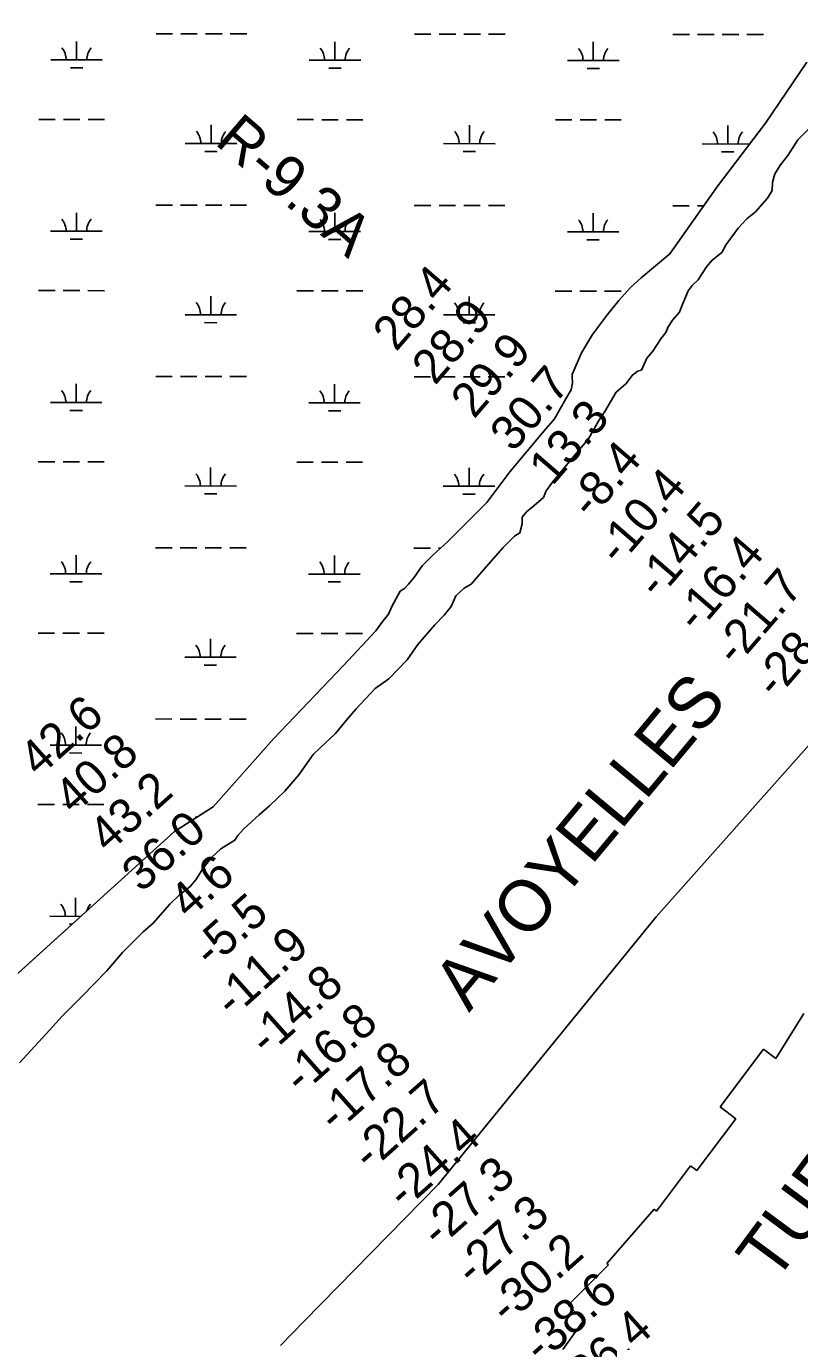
# Model space of a CAD drawing. Extents: x 3148686 to 3186545, y 916144 to 941516.
# Drawn here: x 3155629 to 3157131, y 922106 to 924661 of the extents above; entities that cross this region are included whole.
import ezdxf

# ---------------------------------------------------------------- set-up
doc = ezdxf.new("R2010")
doc.units = 0
for name, color, linetype in [('V-RIVR-EDGE', 7, 'Continuous'), ('V-RIVR-RANG', 7, 'Continuous'), ('V-RIVR-RANG-IDEN', 7, 'Continuous'), ('V-RRAP-RVMT', 7, 'Continuous'), ('V-RRAP-RVMT-IDEN', 7, 'Continuous'), ('V-SITE-VEGE', 7, 'Continuous'), ('V-TOPO-BNDY', 7, 'Continuous'), ('V-TOPO-GNAM-IDEN', 7, 'Continuous'), ('V-WETL-SWMP', 7, 'Continuous')]:
    doc.layers.add(name, color=color, linetype=linetype)

msp = doc.modelspace()

# ---------------------------------------------------------------- linework, layer by layer
at = {"layer": 'V-RIVR-EDGE'}
for points in [[(3157165.5, 924478.7), (3157127.5, 924440.5), (3157108.3, 924409.7), (3157093.7, 924392), (3157082.7, 924374), (3157078.4, 924358.4), (3157077.6, 924341.7), (3157068.4, 924326.9), (3157045.2, 924300.7), (3157028.2, 924287.2), (3157011.5, 924268.8), (3156988.3, 924237.3), (3156979.8, 924221.8), (3156961.3, 924206.6), (3156949.9, 924193.8), (3156941.8, 924180.4), (3156933.9, 924168.7), (3156922.2, 924157.4), (3156914.7, 924147.1), (3156901.5, 924115.9), (3156897.6, 924105.7), (3156884.4, 924090.1), (3156875.5, 924077), (3156871.3, 924066), (3156861.7, 924053.6), (3156846, 924029.9), (3156833.9, 924016.1), (3156829.3, 924004.4), (3156823.6, 923992.7), (3156816.1, 923991.3), (3156805.5, 923982.8), (3156794.1, 923966.9), (3156774.9, 923949.9), (3156752.8, 923912.8), (3156741.1, 923895.4), (3156720.8, 923859.3), (3156686.3, 923818.6), (3156651, 923775.1), (3156638.6, 923758.4), (3156633.2, 923745.3), (3156614.8, 923729.4), (3156600.6, 923718.1), (3156592, 923707.1), (3156592, 923694.7), (3156587.3, 923676.7), (3156577.4, 923670.7), (3156555.4, 923648.7), (3156517.7, 923605.9), (3156492.8, 923577.6), (3156479.6, 923569.5), (3156463.3, 923554.6), (3156454.4, 923534.1)], [(3156454.4, 923534.1), (3156440.8, 923517.1), (3156422.4, 923498), (3156389.6, 923459.8), (3156368.6, 923430.4), (3156332.7, 923393.3), (3156306.5, 923374.5), (3156269.5, 923335.3), (3156249.9, 923312.6), (3156229.7, 923287.5), (3156199.8, 923259.6), (3156186.3, 923246.5), (3156158.2, 923206.8), (3156131.2, 923175.3), (3156101.3, 923147), (3156081, 923129.4), (3156051.2, 923102.1), (3156039.5, 923089.4), (3156033.8, 923079.8), (3156006.8, 923063.2), (3155989, 923047.3), (3155972.6, 923025.4), (3155958, 923003.1), (3155947.4, 922990), (3155926.4, 922974.1), (3155907.6, 922955.7), (3155875.2, 922918.9), (3155856, 922901.9), (3155815.9, 922861.6), (3155784.9, 922826.2), (3155736.9, 922776.3), (3155698.9, 922738.8), (3155667.2, 922703.8), (3155615.3, 922647.6)]]:
    msp.add_lwpolyline(points, dxfattribs=at)
at = {"layer": 'V-RRAP-RVMT'}
for p, q in [((3157084.6, 922656.1), (3157139.3, 922743.6)), ((3156976.6, 922561.9), (3157061.1, 922673.9)), ((3157061.1, 922673.9), (3157084.6, 922656.1)), ((3157007.4, 922538.8), (3156976.6, 922561.9)), ((3156931.6, 922438.2), (3157007.4, 922538.8)), ((3156852.7, 922359.6), (3156919.1, 922447.6)), ((3156919.1, 922447.6), (3156931.6, 922438.2)), ((3156756.6, 922257.6), (3156848.5, 922363.3)), ((3156848.5, 922363.3), (3156852.7, 922359.6)), ((3156681.4, 922177), (3156759.5, 922255)), ((3156759.5, 922255), (3156756.6, 922257.6)), ((3156711.5, 922146.9), (3156681.4, 922177)), ((3156671.1, 922090.6), (3156711.5, 922146.9))]:
    msp.add_line(p, q, dxfattribs=at)
at = {"layer": 'V-SITE-VEGE'}
for p, q in [((3157064.5, 924472.8), (3157145.2, 924591)), ((3156972.1, 924350.8), (3157064.5, 924472.8)), ((3156879.2, 924218.9), (3156972.1, 924350.8)), ((3156823.1, 924172.6), (3156879.2, 924218.9)), ((3156802.8, 924153.8), (3156823.1, 924172.6)), ((3156779.6, 924128.5), (3156802.8, 924153.8)), ((3156758, 924101.3), (3156779.6, 924128.5)), ((3156728.9, 924062.5), (3156758, 924101.3)), ((3156707.2, 924026.9), (3156728.9, 924062.5)), ((3156689, 923984.8), (3156707.2, 924026.9)), ((3156687, 923954.8), (3156689.8, 923968.4)), ((3156689.3, 923980.3), (3156689, 923984.8)), ((3156689.8, 923968.4), (3156689.3, 923980.3)), ((3156676.6, 923937.5), (3156687, 923954.8)), ((3156654.8, 923898.1), (3156676.6, 923937.5)), ((3156631, 923870.8), (3156654.8, 923898.1)), ((3156568, 923795.5), (3156631, 923870.8)), ((3156523.7, 923735.6), (3156568, 923795.5)), ((3156446.9, 923659.6), (3156523.7, 923735.6)), ((3156418.8, 923633.8), (3156446.9, 923659.6)), ((3156397.7, 923612.6), (3156418.8, 923633.8)), ((3156381.8, 923589.9), (3156397.7, 923612.6)), ((3156371.5, 923577.1), (3156381.8, 923589.9)), ((3156339.1, 923533.7), (3156355.3, 923563.5)), ((3156355.3, 923563.5), (3156363.3, 923568.9)), ((3156363.3, 923568.9), (3156371.5, 923577.1)), ((3156332.2, 923519.2), (3156339.1, 923533.7)), ((3156319.7, 923503), (3156332.2, 923519.2)), ((3156244.8, 923419.4), (3156307.5, 923486.9)), ((3156307.5, 923486.9), (3156319.7, 923503)), ((3156109, 923276.9), (3156244.8, 923419.4)), ((3155992, 923145), (3156109, 923276.9)), ((3155916.4, 923097.1), (3155992, 923145)), ((3155545.1, 922760.8), (3155916.4, 923097.1))]:
    msp.add_line(p, q, dxfattribs=at)
at = {"layer": 'V-TOPO-BNDY'}
msp.add_lwpolyline([(3156122.4, 922098.2), (3156168.8, 922145.8), (3156428.7, 922411), (3156852.6, 922931.2), (3157254.5, 923382.8), (3157305.3, 923439.5), (3157317.3, 923453.1), (3157677.4, 924009.7), (3157746.6, 924116.6), (3157949.7, 924442.8), (3158078.5, 924650.3), (3158117.2, 924712.4), (3158363.3, 925108.2), (3158430.5, 925235.2), (3158537.2, 925435.5), (3158721.6, 925781.3), (3158837.1, 925997.9), (3159006.2, 926311.1), (3159280.9, 926819.7)], dxfattribs=at)
at = {"layer": 'V-WETL-SWMP'}
for p, q in [((3155726.3, 924595.5), (3155726.4, 924631.5)), ((3155881, 924646.1), (3155913, 924646)), ((3155929, 924646), (3155961, 924646)), ((3155977, 924646), (3156009, 924645.9)), ((3156025, 924645.9), (3156057, 924645.9)), ((3156228.3, 924595), (3156228.3, 924631)), ((3156382.9, 924645.5), (3156414.9, 924645.5)), ((3156430.9, 924645.5), (3156462.9, 924645.4)), ((3156478.9, 924645.4), (3156510.9, 924645.4)), ((3156526.9, 924645.4), (3156558.9, 924645.3)), ((3156730.2, 924594.4), (3156730.2, 924630.4)), ((3156884.8, 924645), (3156916.8, 924645)), ((3156932.8, 924645), (3156964.8, 924644.9)), ((3156980.8, 924644.9), (3157012.8, 924644.9)), ((3157028.8, 924644.9), (3157060.8, 924644.8)), ((3155676.3, 924595.5), (3155776.3, 924595.4)), ((3155714.3, 924580.1), (3155738.3, 924580)), ((3156178.3, 924595), (3156278.3, 924594.9)), ((3156216.2, 924579.5), (3156240.2, 924579.5)), ((3156680.2, 924594.5), (3156780.2, 924594.4)), ((3156718.1, 924579), (3156742.1, 924579)), ((3155652.8, 924480.1), (3155684.8, 924480.1)), ((3155700.8, 924480.1), (3155732.8, 924480)), ((3155748.8, 924480), (3155780.8, 924480)), ((3156154.7, 924479.6), (3156186.7, 924479.6)), ((3156202.7, 924479.5), (3156234.7, 924479.5)), ((3156250.7, 924479.5), (3156282.7, 924479.5)), ((3156656.6, 924479.1), (3156688.6, 924479)), ((3156704.6, 924479), (3156736.6, 924479)), ((3156752.6, 924479), (3156784.6, 924478.9)), ((3155987.6, 924433.3), (3155987.6, 924469.3)), ((3156489.5, 924432.8), (3156489.6, 924468.8)), ((3156991.4, 924432.3), (3156991.5, 924468.3)), ((3155937.6, 924433.4), (3156037.6, 924433.3)), ((3156439.5, 924432.9), (3156539.5, 924432.8)), ((3156941.4, 924432.3), (3157033.8, 924432.2)), ((3155975.6, 924417.9), (3155999.6, 924417.9)), ((3156477.5, 924417.4), (3156501.5, 924417.4)), ((3156979.4, 924416.9), (3157003.4, 924416.8)), ((3155726, 924262.8), (3155726, 924298.8)), ((3155880.6, 924313.4), (3155912.6, 924313.4)), ((3155928.6, 924313.3), (3155960.6, 924313.3)), ((3155976.6, 924313.3), (3156008.6, 924313.3)), ((3156024.6, 924313.2), (3156056.6, 924313.2)), ((3156227.9, 924262.3), (3156227.9, 924298.3)), ((3156382.5, 924312.9), (3156414.5, 924312.8)), ((3156430.5, 924312.8), (3156462.5, 924312.8)), ((3156478.5, 924312.8), (3156510.5, 924312.7)), ((3156526.5, 924312.7), (3156558.5, 924312.7)), ((3156729.8, 924261.7), (3156729.8, 924297.7)), ((3156884.5, 924312.3), (3156916.5, 924312.3)), ((3156932.5, 924312.3), (3156945, 924312.3)), ((3155676, 924262.9), (3155776, 924262.8)), ((3155714, 924247.4), (3155738, 924247.4)), ((3156177.9, 924262.3), (3156277.9, 924262.2)), ((3156215.9, 924246.9), (3156239.9, 924246.8)), ((3156679.8, 924261.8), (3156779.8, 924261.7)), ((3156717.8, 924246.3), (3156741.8, 924246.3)), ((3155652.5, 924147.5), (3155684.5, 924147.4)), ((3155700.5, 924147.4), (3155732.5, 924147.4)), ((3155748.5, 924147.4), (3155780.5, 924147.3)), ((3156154.4, 924146.9), (3156186.4, 924146.9)), ((3156202.4, 924146.9), (3156234.4, 924146.8)), ((3156250.4, 924146.8), (3156282.4, 924146.8)), ((3156656.3, 924146.4), (3156688.3, 924146.4)), ((3156704.3, 924146.3), (3156736.3, 924146.3)), ((3156752.3, 924146.3), (3156784.3, 924146.3)), ((3155987.3, 924100.7), (3155987.3, 924136.7)), ((3156489.2, 924100.1), (3156489.2, 924136.1)), ((3155937.3, 924100.7), (3156037.3, 924100.6)), ((3156439.2, 924100.2), (3156539.2, 924100.1)), ((3155975.2, 924085.3), (3155999.2, 924085.2)), ((3156477.2, 924084.7), (3156501.2, 924084.7)), ((3155725.6, 923930.1), (3155725.7, 923966.1)), ((3155880.3, 923980.7), (3155912.3, 923980.7)), ((3155928.3, 923980.7), (3155960.3, 923980.6)), ((3155976.3, 923980.6), (3156008.3, 923980.6)), ((3156024.3, 923980.6), (3156056.3, 923980.5)), ((3156227.6, 923929.6), (3156227.6, 923965.6)), ((3156382.2, 923980.2), (3156414.2, 923980.1)), ((3156430.2, 923980.1), (3156462.2, 923980.1)), ((3156478.2, 923980.1), (3156510.2, 923980)), ((3156526.2, 923980), (3156558.2, 923980)), ((3155675.6, 923930.2), (3155775.6, 923930.1)), ((3155713.6, 923914.7), (3155737.6, 923914.7)), ((3156177.6, 923929.7), (3156277.6, 923929.6)), ((3156215.5, 923914.2), (3156239.5, 923914.2)), ((3155652.1, 923814.8), (3155684.1, 923814.7)), ((3155700.1, 923814.7), (3155732.1, 923814.7)), ((3155748.1, 923814.7), (3155780.1, 923814.6)), ((3156154, 923814.2), (3156186, 923814.2)), ((3156202, 923814.2), (3156234, 923814.2)), ((3156250, 923814.1), (3156282, 923814.1)), ((3155986.9, 923768), (3155986.9, 923804)), ((3156488.8, 923767.5), (3156488.9, 923803.5)), ((3155936.9, 923768), (3156036.9, 923767.9)), ((3156438.8, 923767.5), (3156538.8, 923767.4)), ((3155974.9, 923752.6), (3155998.9, 923752.6)), ((3156476.8, 923752), (3156500.8, 923752)), ((3155725.3, 923597.5), (3155725.3, 923633.5)), ((3155879.9, 923648), (3155911.9, 923648)), ((3155927.9, 923648), (3155959.9, 923648)), ((3155975.9, 923647.9), (3156007.9, 923647.9)), ((3156023.9, 923647.9), (3156055.9, 923647.9)), ((3156227.2, 923596.9), (3156227.2, 923632.9)), ((3156381.8, 923647.5), (3156413.8, 923647.5)), ((3156429.8, 923647.5), (3156433.7, 923647.5)), ((3155675.3, 923597.5), (3155775.3, 923597.4)), ((3155713.3, 923582), (3155737.3, 923582)), ((3156177.2, 923597), (3156277.2, 923596.9)), ((3156215.2, 923581.5), (3156239.2, 923581.5)), ((3155651.8, 923482.1), (3155683.8, 923482.1)), ((3155699.8, 923482.1), (3155731.8, 923482)), ((3155747.8, 923482), (3155779.8, 923482)), ((3156153.7, 923481.6), (3156185.7, 923481.5)), ((3156201.7, 923481.5), (3156233.7, 923481.5)), ((3156249.7, 923481.5), (3156281.7, 923481.4)), ((3155986.6, 923435.3), (3155986.6, 923471.3)), ((3155936.6, 923435.4), (3156036.6, 923435.3)), ((3155974.5, 923419.9), (3155998.5, 923419.9)), ((3155724.9, 923264.8), (3155725, 923300.8)), ((3155879.6, 923315.4), (3155911.6, 923315.3)), ((3155927.6, 923315.3), (3155959.6, 923315.3)), ((3155975.6, 923315.3), (3156007.6, 923315.2)), ((3156023.6, 923315.2), (3156055.6, 923315.2)), ((3155674.9, 923264.8), (3155774.9, 923264.7)), ((3155712.9, 923249.4), (3155736.9, 923249.3)), ((3155651.4, 923149.4), (3155683.4, 923149.4)), ((3155699.4, 923149.4), (3155731.4, 923149.3)), ((3155747.4, 923149.3), (3155779.4, 923149.3)), ((3155724.6, 922932.1), (3155724.6, 922968.1)), ((3155674.6, 922932.2), (3155734.2, 922932.1)), ((3155712.6, 922916.7), (3155717.2, 922916.7))]:
    msp.add_line(p, q, dxfattribs=at)
msp.add_lwpolyline([(3155545.1, 922760.8), (3155916.4, 923097.1), (3155992, 923145), (3156109, 923276.9), (3156244.8, 923419.4), (3156307.5, 923486.9), (3156319.7, 923503), (3156332.2, 923519.2), (3156339.1, 923533.7), (3156355.3, 923563.5), (3156363.3, 923568.9), (3156371.5, 923577.1), (3156381.8, 923589.9), (3156397.7, 923612.6), (3156418.8, 923633.8), (3156446.9, 923659.6), (3156523.7, 923735.6), (3156568, 923795.5), (3156631, 923870.8), (3156654.8, 923898.1), (3156676.6, 923937.5), (3156687, 923954.8), (3156689.8, 923968.4), (3156689.3, 923980.3), (3156689, 923984.8), (3156707.2, 924026.9), (3156728.9, 924062.5), (3156758, 924101.3), (3156779.6, 924128.5), (3156802.8, 924153.8), (3156823.1, 924172.6), (3156879.2, 924218.9), (3156972.1, 924350.8), (3157064.5, 924472.8), (3157145.2, 924591)], dxfattribs=at)
for centre, start, end in [((3155671.1, 924596), 359.1678, 40.7115), ((3155781.6, 924595.9), 139.1678, 180.7115), ((3156173, 924595.5), 359.1678, 40.7115), ((3156283.5, 924595.4), 139.1678, 180.7115), ((3156674.9, 924595), 359.1678, 40.7115), ((3156785.4, 924594.8), 139.1678, 180.7115), ((3155932.4, 924433.9), 359.1678, 40.7115), ((3156042.9, 924433.8), 139.1678, 180.7115), ((3156434.3, 924433.3), 359.1678, 40.7115), ((3156544.8, 924433.2), 139.1678, 180.7115), ((3156936.2, 924432.8), 359.1678, 40.7115), ((3157046.7, 924432.7), 139.1678, 180.7115), ((3155670.8, 924263.3), 359.1678, 40.7115), ((3155781.2, 924263.2), 139.1678, 180.7115), ((3156172.7, 924262.8), 359.1678, 40.7115), ((3156283.1, 924262.7), 139.1678, 180.7115), ((3156674.6, 924262.3), 359.1678, 40.7115), ((3156785.1, 924262.2), 139.1678, 180.7115), ((3155932, 924101.2), 359.1678, 40.7115), ((3156042.5, 924101.1), 139.1678, 180.7115), ((3156433.9, 924100.7), 359.1678, 40.7115), ((3156544.4, 924100.6), 139.1678, 180.7115), ((3155670.4, 923930.7), 359.1678, 40.7115), ((3155780.9, 923930.5), 139.1678, 180.7115), ((3156172.3, 923930.1), 359.1678, 40.7115), ((3156282.8, 923930), 139.1678, 180.7115), ((3155931.7, 923768.5), 359.1678, 40.7115), ((3156042.2, 923768.4), 139.1678, 180.7115), ((3156433.6, 923768), 359.1678, 40.7115), ((3156544.1, 923767.9), 139.1678, 180.7115), ((3155670.1, 923598), 359.1678, 40.7115), ((3155780.5, 923597.9), 139.1678, 180.7115), ((3156172, 923597.5), 359.1678, 40.7115), ((3156282.4, 923597.3), 139.1678, 180.7115), ((3155931.3, 923435.9), 359.1678, 40.7115), ((3156041.8, 923435.7), 139.1678, 180.7115), ((3155669.7, 923265.3), 359.1678, 40.7115), ((3155780.2, 923265.2), 139.1678, 180.7115), ((3155931, 923103.2), 36.6626, 40.7115), ((3155669.3, 922932.6), 359.1678, 40.7115), ((3155779.8, 922932.5), 139.1678, 162.9232)]:
    msp.add_arc(centre, 35.2, start, end, dxfattribs=at)

# ---------------------------------------------------------------- texts
at = {"layer": 'V-RIVR-RANG'}
for s, rotation, p in [('28.4', 49.1683, (3156347.2, 924027.3)), ('28.9', 49.1683, (3156422.8, 923961.9)), ('29.9', 49.1683, (3156498.6, 923896.7)), ('30.7', 49.1683, (3156574.6, 923831.7)), ('13.3', 49.1683, (3156650.5, 923766.5)), ('-8.4', 49.1683, (3156726.3, 923701.3)), ('-10.4', 49.1683, (3156780.4, 923610.9)), ('-14.5', 49.1683, (3156856.2, 923545.7)), ('-16.4', 49.1683, (3156932, 923480.5)), ('-21.7', 49.1683, (3157007.8, 923415.3)), ('-28.1', 49.1683, (3157085.2, 923351.9)), ('42.6', 41.6983, (3155652.8, 923200.9)), ('40.8', 41.6983, (3155720.9, 923127.6)), ('43.2', 41.6983, (3155787.6, 923053.1)), ('36.0', 41.6983, (3155852.2, 922976.7)), ('4.6', 41.6983, (3155944.5, 922925)), ('-5.5', 41.6983, (3155987.8, 922829.6)), ('-11.9', 41.6983, (3156029.5, 922732.8)), ('-14.8', 41.6983, (3156096.4, 922658.5)), ('-16.8', 41.6983, (3156163.1, 922584)), ('-17.8', 41.6983, (3156229.8, 922509.5)), ('-22.7', 41.6983, (3156296.5, 922435)), ('-24.4', 41.6983, (3156363.2, 922360.5)), ('-27.3', 41.6983, (3156429.9, 922286)), ('-27.3', 41.6983, (3156496.6, 922211.5)), ('-30.2', 41.6983, (3156563.3, 922137.1)), ('-38.6', 41.6983, (3156628.7, 922061.3)), ('-26.4', 41.6983, (3156696.8, 921988.1))]:
    msp.add_text(s, height=67, rotation=rotation, dxfattribs=at).set_placement(p)
at = {"layer": 'V-RIVR-RANG-IDEN'}
msp.add_text('R-9.3A', height=83, rotation=319.3081, dxfattribs=at).set_placement((3155992.8, 924433.5))
at = {"layer": 'V-RRAP-RVMT-IDEN'}
msp.add_text('TURNBULL', height=100, rotation=53.4608, dxfattribs=at).set_placement((3157083, 922218.1))
at = {"layer": 'V-TOPO-GNAM-IDEN'}
msp.add_text('AVOYELLES', height=100, rotation=50.2207, dxfattribs=at).set_placement((3156488.8, 922744.1))

doc.saveas('drawing.dxf')
